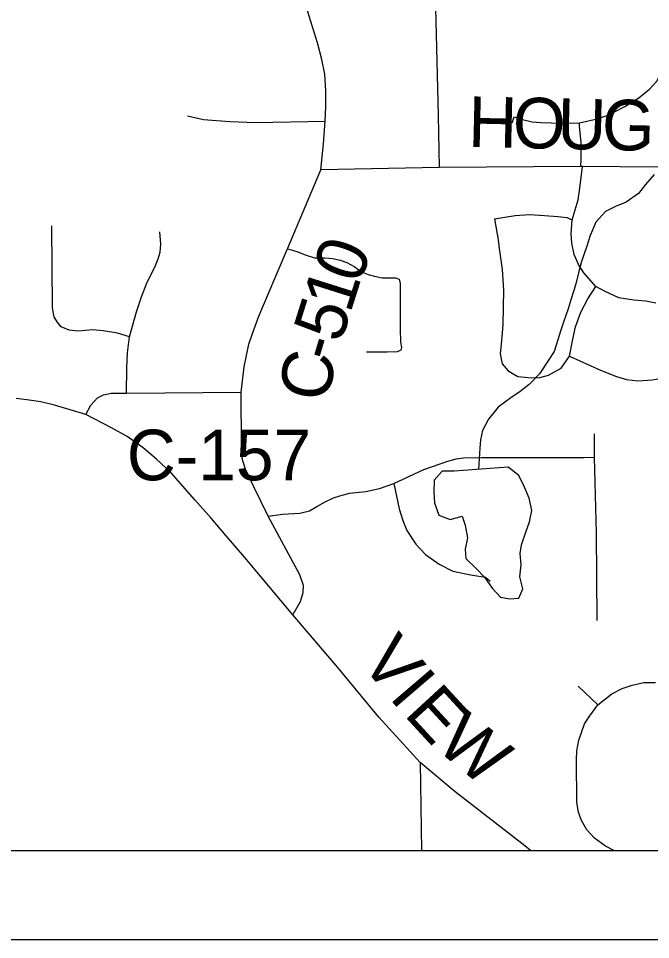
# Model space of a CAD drawing. Extents: x 0 to 34, y 0 to 22.
# Drawn here: x 2.535 to 3.245, y 14 to 15.034 of the extents above; entities that cross this region are included whole.
import ezdxf

# ---------------------------------------------------------------- set-up
doc = ezdxf.new("R2010")
doc.units = 0
for name, color, linetype in [('GM_X_County_Road', 7, 'Continuous'), ('GM_X_County_Road_Text', 7, 'Continuous'), ('GM_X_County_Text', 7, 'Continuous'), ('GM_X_Minor_Lake', 7, 'Continuous'), ('GM_X_Minor_River', 7, 'Continuous'), ('GM_X_Township_Road', 7, 'Continuous'), ('GM_X_Township_Road_Text', 7, 'Continuous'), ('SH_Cut_Line', 7, 'Continuous'), ('SH_Data', 7, 'Continuous')]:
    doc.layers.add(name, color=color, linetype=linetype)

msp = doc.modelspace()

# ---------------------------------------------------------------- linework, layer by layer
at = {"layer": 'GM_X_County_Road'}
for points in [[(2.7853, 14.6146), (2.7885, 14.6432), (2.7938, 14.6688), (2.798, 14.6807), (2.8051, 14.7), (2.8348, 14.7698), (2.8373, 14.7757), (2.8745, 14.8645), (2.8777, 14.8935), (2.8795, 14.9189), (2.8804, 14.935), (2.8804, 14.953), (2.8791, 14.9719), (2.8758, 14.9882), (2.8708, 15.0071), (2.856, 15.0553)], [(3.1099, 14.1), (3.1036, 14.1052), (3.0254, 14.1658), (2.9862, 14.199), (2.9398, 14.2498), (2.8937, 14.3057), (2.8433, 14.3646), (2.7895, 14.4291), (2.7683, 14.4533), (2.7514, 14.4733), (2.7334, 14.494), (2.7066, 14.5243), (2.6903, 14.5394), (2.6752, 14.5524), (2.6572, 14.565), (2.6397, 14.5747), (2.6109, 14.5895), (2.5758, 14.6001), (2.5605, 14.604), (2.5446, 14.6062), (2.5328, 14.6077)], [(2.6109, 14.5895), (2.6164, 14.6), (2.6239, 14.6085), (2.6308, 14.6117), (2.6393, 14.6135), (2.6565, 14.6135), (2.7853, 14.6146)], [(2.8433, 14.3646), (2.852, 14.3797), (2.8547, 14.3896), (2.8552, 14.3975), (2.8512, 14.4095), (2.8155, 14.4756), (2.7994, 14.5084), (2.7901, 14.5282), (2.7871, 14.5378), (2.7855, 14.5454), (2.7855, 14.5537), (2.7853, 14.6146)]]:
    msp.add_lwpolyline(points, dxfattribs=at)
at = {"layer": 'GM_X_County_Text'}
msp.add_lwpolyline([(2.1, 15.3556), (2.1, 14.1), (4.3787, 14.1), (4.3725, 14.1373), (4.3676, 14.1533), (4.4185, 14.2906), (4.4707, 14.5032), (4.0058, 14.5086), (4.0092, 14.8604), (4.002, 15.1777), (4.1154, 15.1803), (4.1171, 15.3509), (3.8077, 15.3535), (3.6529, 15.3542), (3.32, 15.3518), (3.0143, 15.3554), (2.8413, 15.3568), (2.5967, 15.3568)], close=True, dxfattribs=at)
at = {"layer": 'GM_X_Minor_Lake'}
for points in [[(3.0243, 14.5259), (3.011, 14.5261), (3.002, 14.5158), (3.0014, 14.5025), (3.0023, 14.4903), (3.007, 14.4767), (3.0199, 14.4719), (3.0332, 14.4755), (3.0367, 14.4652), (3.0391, 14.4512), (3.0366, 14.4383), (3.0375, 14.428), (3.049, 14.4167), (3.0582, 14.407), (3.067, 14.3945), (3.0762, 14.3844), (3.0869, 14.3826), (3.0967, 14.3835), (3.1012, 14.3938), (3.098, 14.4074), (3.0993, 14.4207), (3.0984, 14.4336), (3.0999, 14.4432), (3.1046, 14.4577), (3.109, 14.4691), (3.1116, 14.482), (3.1084, 14.4957), (3.1033, 14.5082), (3.0967, 14.521), (3.0849, 14.5304)], [(3.0849, 14.5304), (3.0243, 14.5259)]]:
    msp.add_lwpolyline(points, dxfattribs=at)
at = {"layer": 'GM_X_Minor_River'}
msp.add_lwpolyline([(3.2488, 14.859), (3.239, 14.8479), (3.2312, 14.8379), (3.2173, 14.8282), (3.2052, 14.8232), (3.1943, 14.8177), (3.1834, 14.8058), (3.1771, 14.7905), (3.1731, 14.7787), (3.1672, 14.7616), (3.1643, 14.7501), (3.1603, 14.7349), (3.1556, 14.7196), (3.1523, 14.7082), (3.1471, 14.6933), (3.1438, 14.6834), (3.1405, 14.6735), (3.1365, 14.6605), (3.1302, 14.6506), (3.1201, 14.6353), (3.1085, 14.6234), (3.0983, 14.6156), (3.0878, 14.6083), (3.0735, 14.5979), (3.0627, 14.5845), (3.056, 14.5718), (3.0538, 14.5612), (3.0532, 14.5517), (3.0517, 14.5279)], dxfattribs=at)
at = {"layer": 'GM_X_Township_Road'}
for p, q in [((3.1633, 14.2844), (3.1854, 14.2635)), ((2.9862, 14.199), (2.9876, 14.1))]:
    msp.add_line(p, q, dxfattribs=at)
for points in [[(3.0144, 15.3556), (3.0173, 15.2142), (3.0187, 15.1668), (3.0212, 15.1073), (3.0207, 15.099), (3.0181, 15.0901), (3.0145, 15.0818), (3.0078, 15.0691), (3.0051, 15.0615), (3.0036, 15.0553), (3.0032, 15.0465), (3.0065, 14.9255), (3.0076, 14.867)], [(3.0894, 14.9172), (3.0915, 14.924), (3.1008, 14.9208), (3.1119, 14.9183), (3.1215, 14.9176), (3.1332, 14.9172), (3.1543, 14.9169), (3.165, 14.9172), (3.1849, 14.9215), (3.196, 14.9254), (3.2035, 14.9293), (3.2159, 14.9354), (3.2316, 14.9454), (3.2434, 14.955), (3.2519, 14.9639), (3.2584, 14.9764), (3.2633, 14.9903), (3.2662, 15.0006), (3.2673, 15.0088), (3.2669, 15.0252), (3.2673, 15.0473), (3.2673, 15.0719), (3.2673, 15.0858), (3.2675, 15.0945)], [(2.7252, 14.9251), (2.7431, 14.921), (2.7724, 14.9187), (2.8012, 14.9177), (2.8795, 14.9189)], [(3.1666, 14.8681), (3.1669, 14.8763), (3.167, 14.8873), (3.1669, 14.8959), (3.1662, 14.9023), (3.1654, 14.9099), (3.1648, 14.9136), (3.165, 14.9172)], [(4.0094, 14.8598), (3.9115, 14.861), (3.821, 14.8613), (3.6366, 14.8632), (3.628, 14.8639), (3.4647, 14.8648), (3.38, 14.8663), (3.1683, 14.8681), (3.1666, 14.8681), (3.0076, 14.867), (2.8745, 14.8645)], [(3.2505, 14.7146), (3.2393, 14.7168), (3.2258, 14.7181), (3.2091, 14.7207), (3.1931, 14.7281), (3.1832, 14.7335), (3.1697, 14.7489), (3.1639, 14.7582), (3.1591, 14.7694), (3.1562, 14.7819), (3.1556, 14.7928), (3.1569, 14.8082), (3.1633, 14.8306), (3.1655, 14.8438), (3.1683, 14.8681)], [(3.0697, 14.8092), (3.0928, 14.8133), (3.1088, 14.8143), (3.1255, 14.8133), (3.1405, 14.8121), (3.1508, 14.8108), (3.1569, 14.8082)], [(3.0697, 14.8092), (3.0742, 14.7835), (3.0745, 14.7787), (3.078, 14.7524), (3.0796, 14.7293), (3.079, 14.6909), (3.0774, 14.6723), (3.0761, 14.6579), (3.0783, 14.6466), (3.0848, 14.6386), (3.0957, 14.6322), (3.1114, 14.6309), (3.1203, 14.6312), (3.1303, 14.6338), (3.1444, 14.6418), (3.1537, 14.655), (3.1575, 14.6742), (3.1604, 14.688), (3.1665, 14.7047), (3.1742, 14.7194), (3.1832, 14.7335)], [(2.66, 14.677), (2.6463, 14.6811), (2.6303, 14.6837), (2.6186, 14.6846), (2.6023, 14.6834), (2.5923, 14.6844), (2.5831, 14.6881), (2.5789, 14.6936), (2.5755, 14.6992), (2.5743, 14.7051), (2.5736, 14.7099), (2.5726, 14.8017)], [(2.6565, 14.6135), (2.6568, 14.6417), (2.6577, 14.6589), (2.66, 14.677), (2.6676, 14.705), (2.6734, 14.7219), (2.6798, 14.7382), (2.6885, 14.7551), (2.6922, 14.7645), (2.6945, 14.7721), (2.695, 14.7808), (2.6938, 14.7947)], [(2.8373, 14.7757), (2.8478, 14.7726), (2.8583, 14.7687), (2.8675, 14.7657), (2.879, 14.7654), (2.8882, 14.7648), (2.8964, 14.7631), (2.904, 14.7602), (2.9122, 14.7559), (2.9204, 14.75), (2.9277, 14.747), (2.9362, 14.7447), (2.9435, 14.7431), (2.9497, 14.7431), (2.9586, 14.7431), (2.9625, 14.7417), (2.9635, 14.7368), (2.9635, 14.7223), (2.9638, 14.6858), (2.9642, 14.671), (2.9652, 14.6648), (2.9645, 14.6618), (2.9602, 14.6602), (2.949, 14.6595), (2.926, 14.6595)], [(3.1537, 14.655), (3.1886, 14.6393), (3.2063, 14.6322), (3.2178, 14.629), (3.2306, 14.6274), (3.2466, 14.6287), (3.2575, 14.6303), (3.2736, 14.6367), (3.3021, 14.6527), (3.3169, 14.6614)], [(3.1848, 14.3584), (3.1841, 14.4563), (3.1819, 14.5417), (3.1816, 14.5678)], [(2.8155, 14.4756), (2.8318, 14.4777), (2.8509, 14.4788), (2.8618, 14.4816), (2.8703, 14.4862), (2.8797, 14.4914), (2.8887, 14.4962), (2.8958, 14.4984), (2.9069, 14.5014), (2.9252, 14.503), (2.9406, 14.5065), (2.9565, 14.5123), (2.9902, 14.5277), (3.0171, 14.5374), (3.0267, 14.5399), (3.0346, 14.5411), (3.0549, 14.5415), (3.17, 14.5412), (3.1819, 14.5417)], [(2.9565, 14.5123), (2.9627, 14.4837), (2.9666, 14.4706), (2.9713, 14.4594), (2.9812, 14.444), (2.9921, 14.4325), (3.0075, 14.4216), (3.0229, 14.4139), (3.045, 14.4091), (3.0594, 14.4068), (3.0646, 14.4024)], [(3.2035, 14.1), (3.1941, 14.1049), (3.1816, 14.1138), (3.1732, 14.1231), (3.1671, 14.1337), (3.1639, 14.143), (3.162, 14.1539), (3.1617, 14.2017), (3.162, 14.2119), (3.1643, 14.2238), (3.1707, 14.2424), (3.1764, 14.2514), (3.1854, 14.2635), (3.2014, 14.2761), (3.213, 14.2818), (3.2239, 14.2857), (3.237, 14.2886), (3.2502, 14.2886)]]:
    msp.add_lwpolyline(points, dxfattribs=at)
at = {"layer": 'SH_Cut_Line'}
msp.add_lwpolyline([(2.1, 14.1), (8.9, 14.1)], dxfattribs=at)
at = {"layer": 'SH_Data'}
for p, q in [((2.1, 14.1), (8.9, 14.1)), ((2, 14), (9, 14))]:
    msp.add_line(p, q, dxfattribs=at)

# ---------------------------------------------------------------- texts
at = {"layer": 'GM_X_County_Road_Text'}
for s, height, rotation, p in [('0', 0.0568, 69.6376, (2.9178, 14.7347)), ('1', 0.0568, 72.4389, (2.9075, 14.702)), ('5', 0.0568, 72.6413, (2.8971, 14.6686)), ('-', 0.0568, 73.2118, (2.8904, 14.6464)), ('C', 0.0568, 80.6378, (2.8832, 14.6023)), ('C-157', 0.05682, 0, (2.6569, 14.5158)), ('V', 0.0568, 309.2435, (2.9177, 14.3119)), ('I', 0.0568, 310.5856, (2.9502, 14.272)), ('E', 0.0568, 312.6044, (2.9668, 14.2527)), ('W', 0.0568, 320.555, (3.0017, 14.2156))]:
    msp.add_text(s, height=height, rotation=rotation, dxfattribs=at).set_placement(p)
at = {"layer": 'GM_X_Township_Road_Text'}
for s, rotation, p in [('H', 358.7177, (3.0396, 14.8902)), ('O', 358.7201, (3.0896, 14.8891)), ('U', 358.7177, (3.1396, 14.888)), ('G', 358.7182, (3.1896, 14.8869))]:
    msp.add_text(s, height=0.0568, rotation=rotation, dxfattribs=at).set_placement(p)

doc.saveas('drawing.dxf')
